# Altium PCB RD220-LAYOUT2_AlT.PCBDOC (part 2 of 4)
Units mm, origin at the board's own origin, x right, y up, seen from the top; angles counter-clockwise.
Board outline 250 x 145 mm, 4 copper layers (TOP, Mid-Layer 1, Mid-Layer 2, BOTTOM), stack 0.711 mm thick; 497 components, 207 nets, 1178 pads, 436 vias.
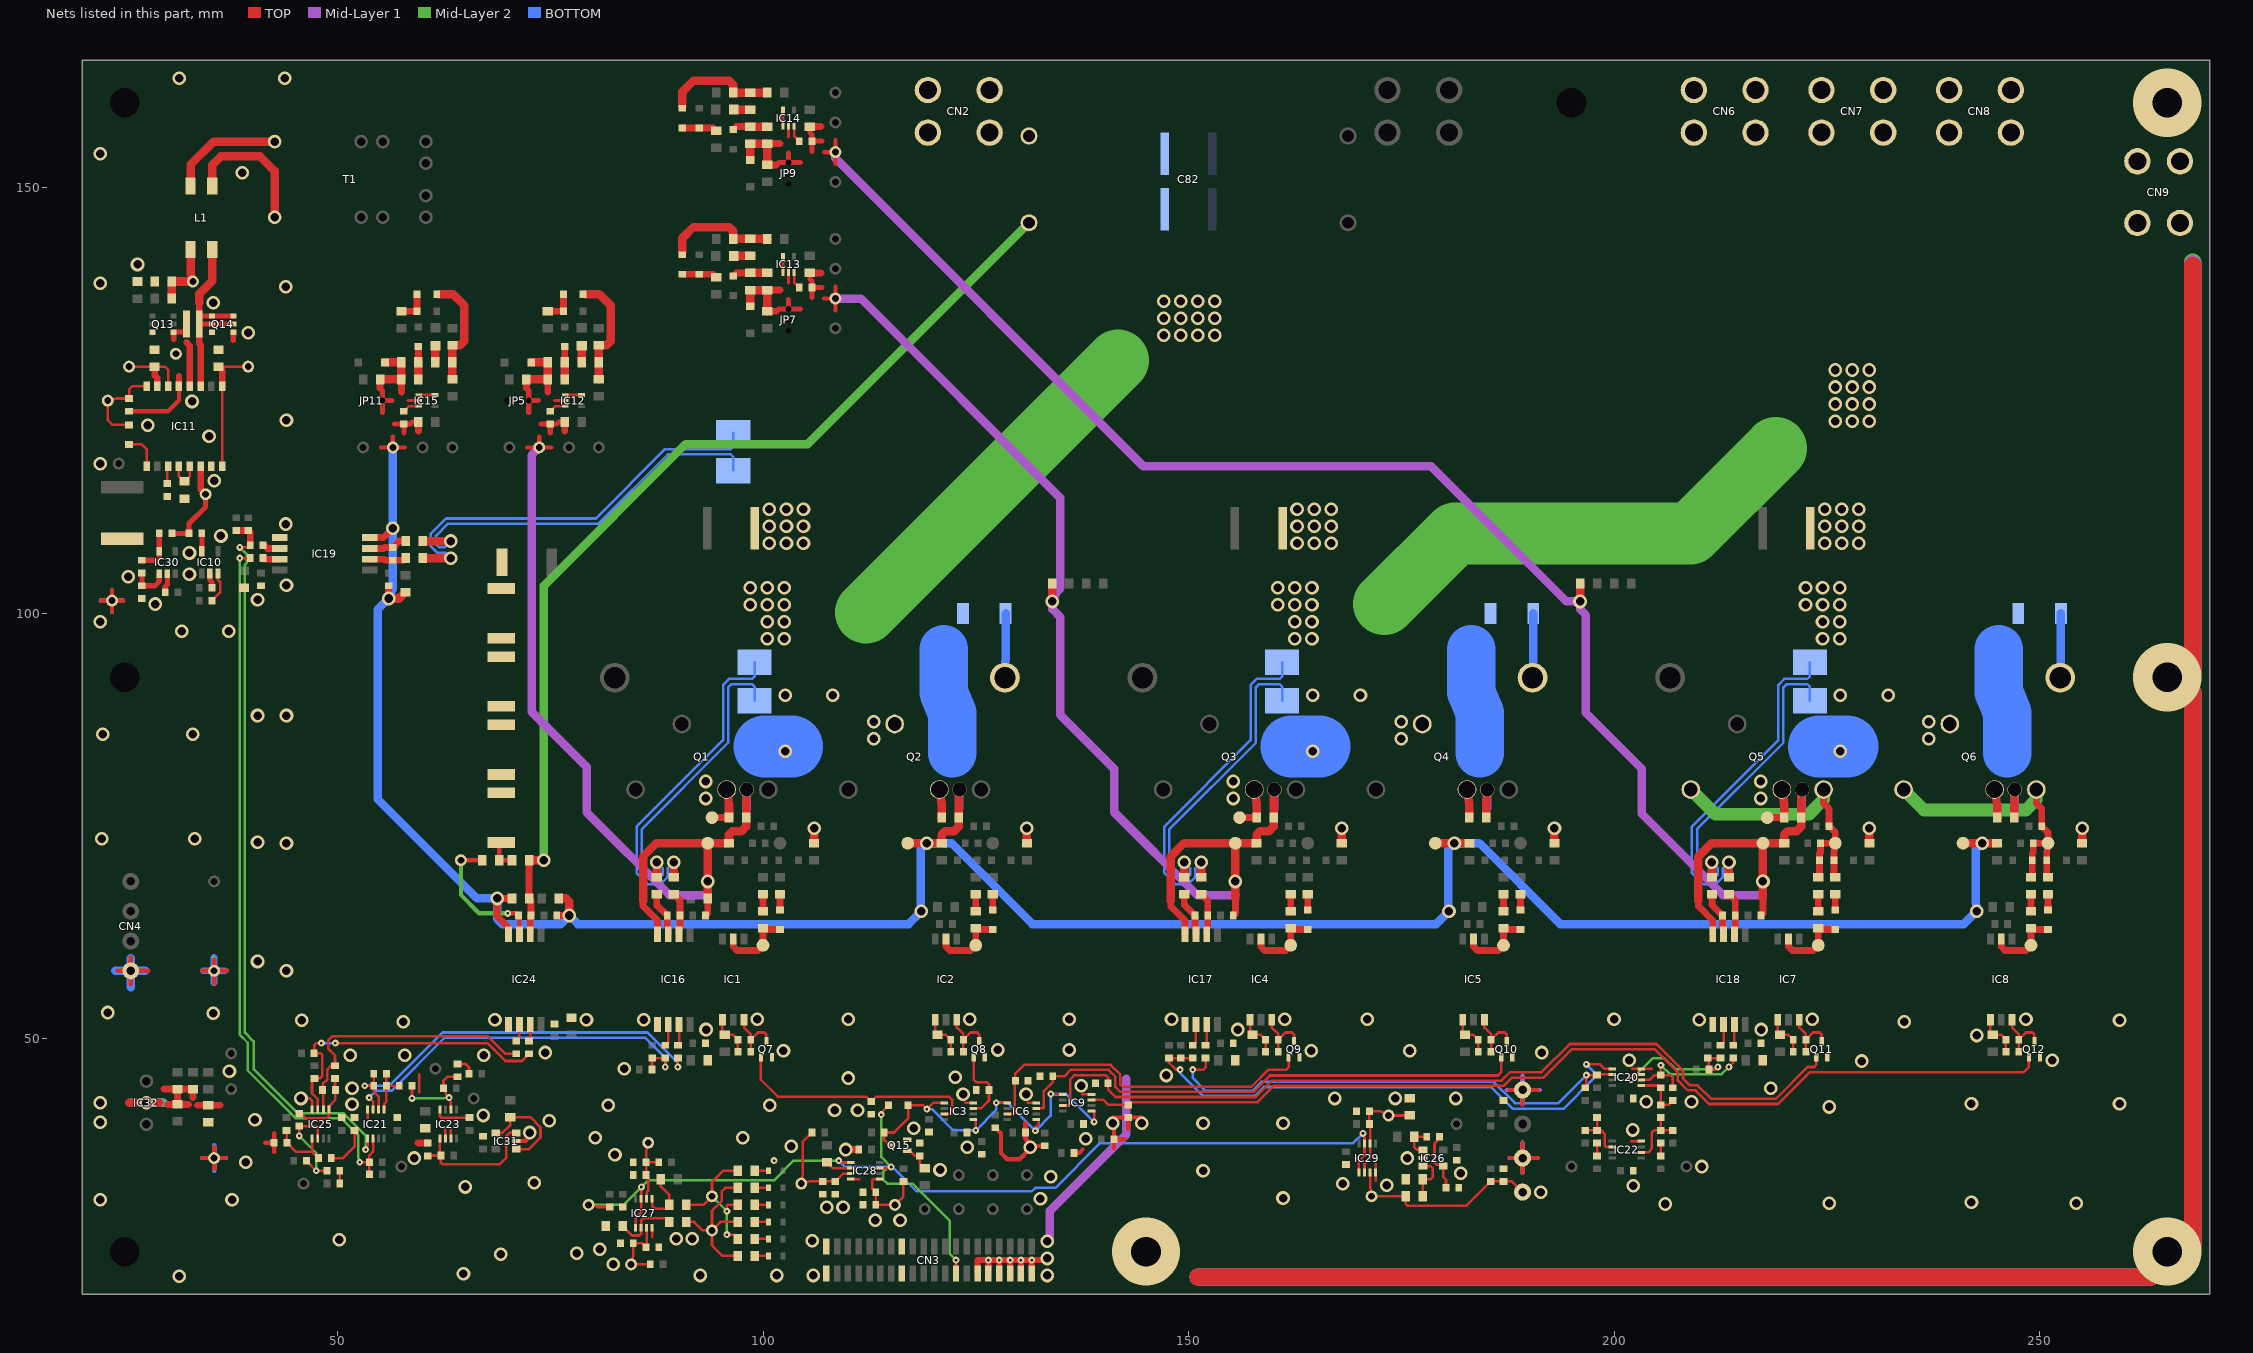
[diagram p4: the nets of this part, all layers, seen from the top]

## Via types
v1: diameter 1.6, hole 1, TOP to BOTTOM, 364 vias
v2: diameter 0.8, hole 0.3, TOP to BOTTOM, 68 vias
v3: diameter 8, hole 3.5, TOP to BOTTOM, 4 vias

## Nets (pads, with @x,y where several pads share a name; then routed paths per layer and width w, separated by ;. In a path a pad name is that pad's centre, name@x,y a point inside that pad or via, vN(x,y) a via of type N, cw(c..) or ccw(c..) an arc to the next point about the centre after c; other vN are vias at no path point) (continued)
G_WH: C145.2 D9.A D10.C Q5.1 Q5.5 R39.1 R40.1 R44.1 TP17.1 | length 35.5
  TOP w0.8: R39.1@224,69 224.15,69.15 D10.C@224.15,71 224.15,71.8 224.25,71.9 R44.1@224.25,73 TP17.1@226,73 ; Q5.5@224.62,79.3 224.62,77.68 225.25,77.05 C145.2@225.25,75 226,74.25 TP17.1@226,73 ; R40.1@226,69 225.85,69.15 D9.A@225.85,71 225.85,71.885 TP17.1@226,73
  Mid-Layer 2 w1.5: Q5.1@209.02,79.3 211.92,76.4 222.9,76.4 224.62,78.12 Q5.5@224.62,79.3
G_WL: C147.2 D11.A D12.C Q6.1 Q6.5 R42.1 R43.1 R45.1 TP20.1 | length 35.1
  TOP w0.8: R42.1@249,69 249.15,69.15 D12.C@249.15,71 249.15,71.8 249.25,71.9 R45.1@249.25,73 TP20.1@251,73 ; Q6.5@249.62,79.3 249.62,77.68 250.25,77.05 C147.2@250.25,75 251,74.25 TP20.1@251,73 ; R43.1@251,69 250.85,69.15 D11.A@250.85,71 250.85,71.885 TP20.1@251,73
  Mid-Layer 2 w1.5: Q6.1@234.02,79.3 236.42,76.9 248.4,76.9 249.62,78.12 Q6.5@249.62,79.3
GND_A: C39.1 C41.1 C42.1 C43.1 C44.1 C46.1 C78.1 C79.1 C98.1 C99.1 C103.1 C104.1 C108.1 C109.1 C113.1 C114.1 C115.1 C117.1 C119.1 C120.1 C121.1 C122.1 C123.1 C128.1 C135.1 C148.1 C149.1 C150.1 C165.2 CN3.29 CN3.31 CN3.33 CN3.35 CN3.37 CN3.39 CN4.4 IC10.2 IC11.7 IC16.5 IC17.5 IC18.5 IC19.5 IC20.4 IC21.4 IC22.4 IC23.4 IC24.5 IC25.4 IC30.2 IC31.2 IC32.2 J2.1 J4.1 Q7.S Q8.S Q9.S Q10.S Q11.S Q12.S Q14.4 R122.2 R154.1 R186.2 R188.2 TP28.1 TP71.1 | length 204
  TOP w0.3: v1(45.7,43) 46.75,43 47.025,42.725 IC25.4@47.025,41.7 ; 53.525,40.7 IC21.4@53.525,41.7 ; 59.6,43.74 59.6,45.85 ; IC23.4@62.025,41.7 62.025,40.925 62.2,40.75 C123.1@65.5,40.75 ; 202,37.975 IC22.4@203.2,37.975 ; 202.15,46.475 IC20.4@203.2,46.475 204.4,46.475
  TOP w0.5: 22.2,101.5 TP28.1@23.5,101.5 ; 23.5,100.25 TP28.1@23.5,101.5 ; 23.5,102.75 TP28.1@23.5,101.5 ; 24.1,58 CN4.4@25.7,58 ; 24.85,101.5 TP28.1@23.5,101.5 ; 25.7,56.4 CN4.4@25.7,58 ; 25.7,59.6 CN4.4@25.7,58 ; 27.8,58 CN4.4@25.7,58 ; 34.1,58 TP71.1@35.5,58 ; 35.5,56.5 TP71.1@35.5,58 ; 35.5,59.3 TP71.1@35.5,58 ; 37,58 TP71.1@35.5,58 ; 41.5,37.8 C165.2@42.55,37.8 ; 42.55,36.7 C165.2@42.55,37.8 ; 42.55,38.9 C165.2@42.55,37.8 ; IC31.2@71,38 72.15,38 v1(72.6,39) ; 187.7,44 J4.1@189.25,44 ; 187.8,36 J2.1@189.25,36 ; 189.25,34.4 J2.1@189.25,36 ; 189.25,37.8 J2.1@189.25,36 ; 189.25,42.3 J4.1@189.25,44 ; 191,36 J2.1@189.25,36 ; 191,44 J4.1@189.25,44
  TOP w0.6: C128.1@29.75,102.5 29.75,103.15 30,103.4 IC30.2@30,104.685 ; IC10.2@35,104.69 35,103.9 35.25,103.65 C39.1@35.25,103 ; 37.75,132.1 Q14.4@37.75,133.05
  TOP w0.7: CN3.29@125.215,22.481 125.215,24.006 v2(126.485,24.006) ; CN3.31@126.485,22.481 v2(126.485,24.006) ; CN3.33@127.755,22.481 v2(127.755,24.006) ; CN3.35@129.025,22.481 v2(129.025,24.006) ; CN3.37@130.295,22.481 v2(130.295,24.006) ; CN3.39@131.565,22.481 v2(131.565,24.006) ; v1(133.4,24.2) 133.206,24.006 v2(131.565,24.006) ; v2(126.485,24.006) v2(127.755,24.006) ; v2(127.755,24.006) v2(129.025,24.006) ; v2(129.025,24.006) v2(130.295,24.006) ; v2(130.295,24.006) v2(131.565,24.006)
  TOP w0.8: 29.6,44.1 C150.1@31.2,44.1 ; 30.05,42.3 C149.1@31.2,42.3 ; 32.5,42.3 C149.1@31.2,42.3 ; 33,43.1 R186.2@33,44.1 C150.1@31.2,44.1 ; 33.533,42.2 R188.2@34.8,42.2 36.2,42.2 ; 59.45,37.75 R122.2@60.6,37.75 ; C149.1@31.2,42.3 C150.1@31.2,44.1
  TOP w1: 25.5,42.5 IC32.2@27.55,42.5 28.964,42.5
  Mid-Layer 1 w0.5: 22.25,101.5 TP28.1@23.5,101.5 ; 23.5,100.3 TP28.1@23.5,101.5 ; 23.5,102.7 TP28.1@23.5,101.5 ; 24.3,58 CN4.4@25.7,58 ; 24.8,101.5 TP28.1@23.5,101.5 ; 25.7,56.7 CN4.4@25.7,58 ; 25.7,59.6 CN4.4@25.7,58 ; 27.1,58 CN4.4@25.7,58 ; 34.3,58 TP71.1@35.5,58 ; 35.5,56.7 TP71.1@35.5,58 ; 35.5,59.2 TP71.1@35.5,58 ; 37,58 TP71.1@35.5,58 ; 187.4,44 J4.1@189.25,44 ; 187.7,36 J2.1@189.25,36 ; 189.25,34.3 J2.1@189.25,36 ; 189.25,37.8 J2.1@189.25,36 ; 189.25,42.3 J4.1@189.25,44 ; 189.25,45.7 J4.1@189.25,44 ; 190.9,36 J2.1@189.25,36 ; 191.3,44 J4.1@189.25,44
  Mid-Layer 1 w1: 26.1,42.5 IC32.2@27.55,42.5 29.1,42.5 ; v1(133.4,26.2) 133.7,26.2 133.7,29.8 142.7,38.8 142.7,45.3
  Mid-Layer 2 w0.5: 22.3,101.5 TP28.1@23.5,101.5 ; 23.5,100.25 TP28.1@23.5,101.5 ; 23.5,102.75 TP28.1@23.5,101.5 ; 24.3,58 CN4.4@25.7,58 ; 24.75,101.5 TP28.1@23.5,101.5 ; 25.7,56.5 CN4.4@25.7,58 ; 25.7,59.5 CN4.4@25.7,58 ; 27.1,58 CN4.4@25.7,58 ; 34.2,58 TP71.1@35.5,58 ; 35.5,56.6 TP71.1@35.5,58 ; 35.5,59.5 TP71.1@35.5,58 ; 36.8,58 TP71.1@35.5,58 ; 187.7,36 J2.1@189.25,36 ; 187.7,44 J4.1@189.25,44 ; 189.25,34.3 J2.1@189.25,36 ; 189.25,37.8 J2.1@189.25,36 ; 189.25,42.4 J4.1@189.25,44 ; 189.25,45.6 J4.1@189.25,44 ; 190.9,44 J4.1@189.25,44 ; 191,36 J2.1@189.25,36
  Mid-Layer 2 w1: 25.65,42.5 IC32.2@27.55,42.5 29.45,42.5
  BOTTOM w0.5: 22.15,101.5 TP28.1@23.5,101.5 23.5,100.2 ; 187.8,36 J2.1@189.25,36 ; 189.25,34.4 J2.1@189.25,36 ; 189.25,37.7 J2.1@189.25,36 ; 189.25,45.6 J4.1@189.25,44 191,44 ; 190.6,36 J2.1@189.25,36
  BOTTOM w0.8: 34.218,58 TP71.1@35.5,58 ; 35.5,56.6 TP71.1@35.5,58 ; 35.5,59.55 TP71.1@35.5,58 ; 36.75,58 TP71.1@35.5,58
  BOTTOM w1: 23.9,58 CN4.4@25.7,58 ; 25.7,56.05 CN4.4@25.7,58 ; 25.7,59.5 CN4.4@25.7,58 ; 25.85,42.5 IC32.2@27.55,42.5 29.55,42.5 ; 27.4,58 CN4.4@25.7,58
  other v1: 206,30.6 225.3,30.7 254.3,30.7 242,30.8 191.4,32 65,32.6 202.25,32.75 210.3,35 59,36 202.2,39.3 74.9,40.4 40.3,40.5 67.1,41 225.3,42 81.8,42.2 100.8,42.2 51.7,42.3 242,42.4 259.4,42.4 22.1,42.5 203.8,42.6 209.1,42.6 51.7,44.2 218.4,44.2 110,45.4 122.6,45.5 147.4,45.7 37.3,46.2 83.7,46.5 229.1,47.4 201.8,47.5 251.5,47.5 51.5,48.1 57.9,48.1 67.2,48.1 74.4,48.4 191.5,48.4 102.4,48.6 164.4,48.6 176,48.6 127.6,48.7 136,48.7 242.6,50.4 93.3,51.1 155.8,51.1 217.3,51.1 57.7,52 234.1,52 45.8,52.2 259.4,52.2 68.5,52.25 79.25,52.25 86,52.25 210,52.25 99.3,52.3 110,52.3 124.3,52.3 136,52.3 148,52.3 161.3,52.3 171,52.3 200,52.3 223.3,52.3 248.4,52.3 35.4,53 23,53.1 44,58 40.6,59.1 44,73 40.6,73.1 22.3,73.5 33.2,73.5 22.4,85.8 33,85.8 40.6,88 44,88 31.7,97.9 37.2,97.9 22.1,99 28.6,101.1 40.6,101.6 44,103.3 25.4,104.3 32.6,104.6 32.6,107.1 36.3,109.1 43.9,110.5 35.5,115.6 22.1,117.6 34.9,120.8 27.7,122.1 44,122.7 32.9,124.9 39.5,133 35.4,136.5 43.9,138.4 22.1,138.8 26.5,141 38.8,151.8 22.1,154 31.4,162.9 43.8,162.9
GND_B: C25.1 C26.2 C31.1 C32.2 C37.1 C38.2 C70.1 C71.1 C72.1 C74.2 C76.1 C77.1 C96.1 C97.1 IC15.2 IC19.4 IC24.4 JP11.3 Q2.4 Q4.4 Q6.4 R62.1 R65.1 R118.1 R119.1 R120.1 TP9.1 TP15.1 TP21.1 TP43.1 ZD4.C | length 350.7
  TOP w0.35: 58.3,125 IC15.2@59.55,125
  TOP w0.5: 55.1,119.5 TP43.1@56.5,119.5 ; 56.5,120.8 TP43.1@56.5,119.5 ; 57.9,119.5 TP43.1@56.5,119.5
  TOP w0.6: 55.27,123.6 JP11.3@55.27,125 ; 55.27,126.18 JP11.3@55.27,125 ; 56.4,125 JP11.3@55.27,125 ; 56.7,122.25 C71.1@57.8,122.25 ; 57.8,121.2 C71.1@57.8,122.25 ; C72.1@59.5,122.5 58.8,122.5 58.55,122.25 C71.1@57.8,122.25
  TOP w0.8: IC19.4@53.8,108.905 55.405,108.905 v1(56.5,110) ; 55,126.45 C74.2@55,127.5 ; v1(56,101.75) C97.1@56,103.25 ; 57.5,126 C70.1@57.5,127.5 ; 59.5,121.4 C72.1@59.5,122.5 ; IC24.4@70.095,62.3 70.095,63.105 68.75,64.45 v1(68.75,66.5) R65.1@70.5,66.5 ; C77.1@75.75,64.5 v1(77.25,64.5)
  TOP w1: C74.2@55,127.5 C70.1@57.5,127.5 R62.1@57.5,129.5 ZD4.C@55.635,129.5 ; v1(56,101.75) 57.25,101.75 C96.1@58,102.5 ; C76.1@76,66.5 76.85,66.5 77.25,66.1 v1(77.25,64.5) ; TP9.1@117,73 v1(119.25,73) C26.2@121,73 121,74 121.4,74.4 122.45,74.4 123,74.95 R118.1@123,76 123,77.945 Q2.4@123.08,79.3 ; C25.1@131,73 v1(131,74.75) ; TP15.1@179,73 v1(181.25,73) C32.2@183,73 ; R119.1@185,76 185,77.945 Q4.4@185.08,79.3 ; C31.1@193,73 v1(193,74.75) ; TP21.1@241,73 v1(243.25,73) C38.2@245,73 ; R120.1@247,76 247,77.945 Q6.4@247.08,79.3 ; C37.1@255,73 v1(255,74.75)
  Mid-Layer 1 w1: 123.08,77.1 Q2.4@123.08,79.3 ; 185.08,77.1 Q4.4@185.08,79.3 ; 247.08,77.1 Q6.4@247.08,79.3
  BOTTOM w1: TP43.1@56.5,119.5 v1(56.5,110) 56.5,102.841 v1(56,101.75) 54.75,100.5 54.75,78.15 66.4,66.5 v1(68.75,66.5) 68.75,64.1 69.35,63.5 76.25,63.5 v1(77.25,64.5) 78.25,63.5 117.1,63.5 v1(118.6,65) 118.55,66.199 118.55,72.3 v1(119.25,73) 122.15,73 131.65,63.5 179.1,63.5 v1(180.6,65) 180.5,66.196 180.5,72.25 v1(181.25,73) 184.175,73 193.675,63.5 241.1,63.5 v1(242.6,65) 242.5,66.196 242.5,72.25 v1(243.25,73)
GND_D: C88.1 C89.1 C90.1 C91.1 C92.1 C93.1 C94.1 C116.1 C118.1 C124.1 C125.1 C126.1 CN3.1 CN3.2 CN3.15 CN3.16 IC3.4 IC6.4 IC9.4 IC26.2 IC27.4 IC28.4 IC29.4 Q15.S R85.2 R87.2 R89.2 R91.2 R96.2 R98.2 R109.2 R113.2 R115.1 R162.2 R163.2 R164.2 R167.2 R170.2 R171.2 R172.2 R175.2 R178.2 R179.2 R180.2 R183.2 R188.1 TP73.1 | length 53.5
  TOP w0.3: 86.975,26.75 IC27.4@86.975,27.8 ; IC28.4@110.3,33.525 111.3,33.525 ; 123.75,42.475 IC3.4@124.7,42.475 ; 131.1,42.475 IC6.4@132.1,42.475 ; 137.5,43.475 IC9.4@138.6,43.475 ; 171.975,33.35 IC29.4@171.975,34.3 171.975,35.3
  TOP w0.5: 34.1,36 TP73.1@35.5,36 ; 35.5,34.7 TP73.1@35.5,36 ; 35.5,37.3 TP73.1@35.5,36 ; 36.8,36 TP73.1@35.5,36 ; R171.2@127.3,39.55 127.95,38.9 127.95,36.6 128.7,35.85 130.15,35.85 130.63,36.33 v1(131.4,37.25) 132.583,37.45 R170.2@133.1,37.45 ; R179.2@136.55,36.6 137.15,36.6 137.55,37 ; 141.25,37.15 R178.2@141.25,38.2 ; 142.5,38.2 R178.2@141.25,38.2 ; 142.9,39.45 R183.2@142.9,40.75 ; v1(144.5,40.1) 144.5,40.75 R183.2@142.9,40.75 ; R178.2@141.25,38.2 141.25,39.95 v1(141.1,40.1) 141.1,40.75 R183.2@142.9,40.75
  TOP w0.6: 130.85,40.05 C125.1@130.85,39 130.85,38.317 v1(131.4,37.25)
  TOP w0.8: v1(109.7,37) C89.1@111.25,37
  Mid-Layer 1 w0.5: 34.2,36 TP73.1@35.5,36 ; 35.5,34.8 TP73.1@35.5,36 ; 35.5,37.3 TP73.1@35.5,36 ; 36.9,36 TP73.1@35.5,36
  Mid-Layer 2 w0.5: 34.2,36 TP73.1@35.5,36 ; 35.5,34.7 TP73.1@35.5,36 ; 35.5,37.3 TP73.1@35.5,36 ; 36.5,36 TP73.1@35.5,36
  BOTTOM w0.5: 34.1,36 TP73.1@35.5,36 ; 35.5,34.5 TP73.1@35.5,36 ; 35.5,37.5 TP73.1@35.5,36 ; 36.9,36 TP73.1@35.5,36
  other v1: 31.4,22.1 92.6,22.2 101.6,22.2 105.9,22.2 133.4,22.2 64.8,22.4 82.4,23.5 69.2,24.7 78.1,24.8 80.8,25.3 105.8,26.3 50.2,26.4 89.8,26.5 91.7,26.5 113.2,28.7 116.1,28.7 107.5,30.2 109.4,30.2 22.1,31.1 37.6,31.1 132.6,31.2 161.1,31.3 173.3,32.8 168.1,33 73.1,33.1 133.8,33.8 182,34.2 151.7,34.5 120.8,34.6 39.2,35.5 175.7,36 82.6,36.4 124,37.25 103.3,37.4 137.9,38.25 80.3,38.4 97.6,38.4 117.7,39.5 151.7,40.1 161.1,40.1 22.1,40.2 108.4,41.6 111.1,41.6 167.2,43 174.3,43 181.4,43 123.5,43.5 130.9,43.5 137.4,44.5
  other v2: 101.3,35.7
GND_DC: C75.1 C82.3 C82.4 C84.1 C85.1 CN2.1 CN2.2 CN2.3 CN2.4 IC24.2 R4.1 R65.2 R71.2 R102.2 | length 166.6
  TOP w0.8: R71.2@72.5,71 R65.2@72.5,66.5 72.75,66.25 C75.1@72.75,64.5 72.635,64.385 IC24.2@72.635,62.3
  TOP w1: R102.2@60,106.5 v1(63.3,106.5) ; R71.2@72.5,71 v1(74.25,71)
  Mid-Layer 2 w1: v1(74.25,71) 74.25,103.25 90.9,119.9 105.25,119.9 C82.3@131.25,145.9
  BOTTOM w0.3: v1(63.3,106.5) 62.65,107.15 61.7,107.15 60.95,107.9 60.95,109.35 62.75,111.15 80.35,111.15 88.5,119.3 96.2,119.3 96.5,119.6 R4.1@96.5,121.2
GND_F: CN9.1 CN9.2 CN9.3 CN9.4 | length 899.3
  TOP w2: 151.1,22 v3@263.1,22 ; v3@268,25.7 v3@268,90.7 ; v3@268,93.2 268,140.9
  Mid-Layer 1 w2: 151.1,22 v3@263.1,22 ; v3@268,25.7 v3@268,90.7 ; v3@268,93.2 268,141.05
  Mid-Layer 2 w2: 151.1,22 v3@263.1,22 ; v3@268,25.7 v3@268,90.7 ; v3@268,93.2 268,141.3
  BOTTOM w2: 151.1,22 v3@263.1,22 ; v3@268,25.7 v3@268,90.7 ; v3@268,93.2 268,140.9
  other v3: 145,25 265,25 265,92.5 265,160
GND_U: C22.1 C23.2 C49.1 C50.1 C51.1 C53.2 C101.1 C102.1 IC12.2 IC16.4 JP5.3 Q1.4 R27.1 R53.1 TP6.1 TP31.1 ZD1.C | length 127.7
  TOP w0.35: 75.5,125 IC12.2@76.75,125
  TOP w0.5: 72.3,119.5 TP31.1@73.7,119.5 ; 73.7,120.8 TP31.1@73.7,119.5 ; 75.1,119.5 TP31.1@73.7,119.5
  TOP w0.6: 72.47,123.6 JP5.3@72.47,125 ; 72.47,126.18 JP5.3@72.47,125 ; 73.6,125 JP5.3@72.47,125 ; 73.9,122.25 C50.1@75,122.25 ; 75,121.2 C50.1@75,122.25 ; C51.1@76.7,122.5 76,122.5 75.75,122.25 C50.1@75,122.25
  TOP w0.8: 72.2,126.45 C53.2@72.2,127.5 ; 74.7,126 C49.1@74.7,127.5 ; 76.7,121.4 C51.1@76.7,122.5 ; 85.9,66.222 85.9,65.6 87.595,63.905 IC16.4@87.595,62.3 ; C102.1@93.25,64.5 93.5,64.75 C101.1@93.5,66.5
  TOP w1: C53.2@72.2,127.5 C49.1@74.7,127.5 R53.1@74.7,129.5 ZD1.C@72.835,129.5 ; 85.9,66.222 85.9,71.425 87.475,73 TP6.1@93.5,73 ; C101.1@93.5,66.5 v1(93.5,68.5) TP6.1@93.5,73 ; Q1.4@98.08,79.3 98,77.945 R27.1@98,76 98,74.95 97.45,74.4 96.4,74.4 96,74 C23.2@96,73 TP6.1@93.5,73 ; C22.1@106,73 v1(106,74.75)
  Mid-Layer 1 w1: TP31.1@73.7,119.5 72.8,118.6 72.8,88.45 79.27,81.98 79.27,76.63 89,66.9 93,66.9 ; 98.08,77 Q1.4@98.08,79.3
GND_V: C28.1 C29.2 C56.1 C57.1 C58.1 C60.2 C106.1 C107.1 IC13.2 IC17.4 JP7.1 Q3.4 R28.1 R56.1 TP12.1 TP35.1 ZD2.C | length 161.1
  TOP w0.35: 103,138.8 IC13.2@103,140.05
  TOP w0.5: 107.2,137 TP35.1@108.5,137 ; 108.5,135.6 TP35.1@108.5,137 ; 108.5,138.4 TP35.1@108.5,137
  TOP w0.6: 101.82,135.77 JP7.1@103,135.77 ; 103,136.9 JP7.1@103,135.77 ; 104.4,135.77 JP7.1@103,135.77 ; C58.1@105.5,140 105.5,139.3 105.75,139.05 C57.1@105.75,138.3 ; 105.75,137.1 C57.1@105.75,138.3 ; 106.9,138.3 C57.1@105.75,138.3
  TOP w0.8: C60.2@100.5,135.5 101.55,135.5 ; C56.1@100.5,138 102,138 ; C58.1@105.5,140 106.8,140 ; 147.9,66.222 147.9,65.6 149.595,63.905 IC17.4@149.595,62.3 ; C107.1@155.25,64.5 155.5,64.75 155.5,66.5
  TOP w1: ZD2.C@98.5,136.135 R56.1@98.5,138 C56.1@100.5,138 C60.2@100.5,135.5 ; v1(134,101.4) C106.1@134,103.5 ; 147.9,66.222 147.9,71.425 149.475,73 TP12.1@155.5,73 ; 155.5,66.5 v1(155.5,68.5) TP12.1@155.5,73 ; Q3.4@160.08,79.3 160,77.945 R28.1@160,76 160,74.95 159.45,74.4 158.4,74.4 158,74 C29.2@158,73 TP12.1@155.5,73 ; C28.1@168,73 v1(168,74.75)
  Mid-Layer 1 w1: TP35.1@108.5,137 111.5,137 134.93,113.57 134.93,102.93 134.494,102.494 v1(134,101.4) 134,100.5 134.93,99.57 134.93,88.07 141.27,81.73 141.27,76.63 151,66.9 155.5,66.9 ; 160.08,77 Q3.4@160.08,79.3
GND_W: C34.1 C35.2 C63.1 C64.1 C65.1 C67.2 C111.1 C112.1 IC14.2 IC18.4 JP9.1 Q5.4 R29.1 R59.1 TP18.1 TP39.1 ZD3.C | length 222.5
  TOP w0.35: 103,156 IC14.2@103,157.25
  TOP w0.5: 107.2,154.2 TP39.1@108.5,154.2 ; 108.5,152.8 TP39.1@108.5,154.2 ; 108.5,155.6 TP39.1@108.5,154.2
  TOP w0.6: 101.82,152.97 JP9.1@103,152.97 ; 103,154.1 JP9.1@103,152.97 ; 104.4,152.97 JP9.1@103,152.97 ; C65.1@105.5,157.2 105.5,156.5 105.75,156.25 C64.1@105.75,155.5 ; 105.75,154.3 C64.1@105.75,155.5 ; 106.9,155.5 C64.1@105.75,155.5
  TOP w0.8: C67.2@100.5,152.7 101.55,152.7 ; C63.1@100.5,155.2 102,155.2 ; C65.1@105.5,157.2 106.8,157.2 ; 209.9,66.222 209.9,65.6 211.595,63.905 IC18.4@211.595,62.3 ; C112.1@217.25,64.5 217.5,64.75 217.5,66.5
  TOP w1: ZD3.C@98.5,153.335 R59.1@98.5,155.2 C63.1@100.5,155.2 C67.2@100.5,152.7 ; v1(196,101.4) C111.1@196,103.5 ; 209.9,66.222 209.9,71.425 211.475,73 TP18.1@217.5,73 ; 217.5,66.5 v1(217.5,68.5) TP18.1@217.5,73 ; Q5.4@222.08,79.3 222,77.945 R29.1@222,76 222,74.95 221.45,74.4 220.4,74.4 220,74 C35.2@220,73 TP18.1@217.5,73 ; C34.1@230,73 v1(230,74.75)
  Mid-Layer 1 w1: TP39.1@108.5,154.2 108.5,153.475 144.675,117.3 178.5,117.3 194.4,101.4 v1(196,101.4) 196,100.5 196.7,99.8 196.7,88.3 203.27,81.73 203.27,76.43 212.8,66.9 217.5,66.9 ; 222.08,77 Q5.4@222.08,79.3
IDCP: C86.1 C87.1 C127.1 Q2.3 Q4.3 Q6.3 R4.2 R101.2 R118.2 R119.2 R120.2 R158.1 R159.1 R160.1 | length 94.4
  TOP w1: R101.2@60,108.5 v1(63.3,108.5) ; Q2.3@120.72,79.3 121,77.59 R118.2@121,76 ; Q4.3@182.72,79.3 183,77.59 R119.2@183,76 ; Q6.3@244.72,79.3 245,77.59 R120.2@245,76
  BOTTOM w0.3: v1(63.3,108.5) 62.55,107.75 61.95,107.75 61.55,108.15 61.55,109.1 63,110.55 80.65,110.55 88.8,118.7 96.2,118.7 96.5,118.4 R4.2@96.5,116.8
  BOTTOM w5.7: 121.22,95.8 121.22,90.733 122.21,88.343 122.21,83.546 ; 183.22,95.8 183.22,90.733 184.21,88.343 184.21,83.546 ; 245.22,95.8 245.22,90.733 246.21,88.343 246.21,83.546
  other v1: 100.75,108.25 102.75,108.25 104.75,108.25 162.75,108.25 164.75,108.25 166.75,108.25 224.75,108.25 226.75,108.25 228.75,108.25 100.75,110.25 102.75,110.25 104.75,110.25 162.75,110.25 164.75,110.25 166.75,110.25 224.75,110.25 226.75,110.25 228.75,110.25 100.75,112.25 102.75,112.25 104.75,112.25 162.75,112.25 164.75,112.25 166.75,112.25 224.75,112.25 226.75,112.25 228.75,112.25
IUN: CN6.1 CN6.2 CN6.3 CN6.4 R1.2 R104.2 | length 82.3
  TOP w1: R104.2@89.5,69 v1(89.5,70.75)
  Mid-Layer 2 w7.3: 112.1,100.1 141.7,129.7
  BOTTOM w0.3: v1(89.5,70.75) 88.8,70.05 88.8,69.05 87.9,68.15 86.5,68.15 85.15,69.5 85.15,74.95 95.3,85.1 95.3,91.6 96,92.3 98.7,92.3 99,92.6 R1.2@99,94.25
  other v1: 100.5,97 102.5,97 100.5,99 102.5,99 98.5,101 100.5,101 102.5,101 98.5,103 100.5,103 102.5,103 147.1,132.7 149.1,132.7 151.1,132.7 153.1,132.7 147.1,134.7 149.1,134.7 151.1,134.7 153.1,134.7 147.1,136.7 149.1,136.7 151.1,136.7 153.1,136.7
IUP: Q1.3 Q2.2 R1.1 R27.2 R103.2 TP1.1 | length 46
  TOP w0.8: TP1.1@94,76 R27.2@96,76
  TOP w1: R103.2@87.5,69 v1(87.5,70.75) ; Q1.3@95.72,79.3 96,77.59 R27.2@96,76
  BOTTOM w0.3: v1(87.5,70.75) 88.2,70.05 88.2,69.3 87.65,68.75 86.75,68.75 85.75,69.75 85.75,74.65 95.9,84.8 95.9,91.3 96.3,91.7 98.7,91.7 99,91.4 R1.1@99,89.75
  BOTTOM w7.3: 100.15,84.35 103.403,84.35
  other v1: 93.25,78.25 93.25,80.25 102.6,83.8 113,85.25 113,87.25 102.6,90.4 108.2,90.4
IVN: CN7.1 CN7.2 CN7.3 CN7.4 R2.2 R106.2 | length 94
  TOP w1: R106.2@151.5,69 v1(151.5,70.75)
  Mid-Layer 2 w7.3: 173,101.1 181.3,109.4 209,109.4 219,119.4
  BOTTOM w0.3: v1(151.5,70.75) 150.8,70.05 150.8,69.05 149.9,68.15 148.5,68.15 147.15,69.5 147.15,74.95 157.3,85.1 157.3,91.6 158,92.3 160.7,92.3 161,92.6 R2.2@161,94.25
  other v1: 162.5,97 164.5,97 162.5,99 164.5,99 160.5,101 162.5,101 164.5,101 160.5,103 162.5,103 164.5,103 226,122.6 228,122.6 230,122.6 226,124.6 228,124.6 230,124.6 226,126.6 228,126.6 230,126.6 226,128.6 228,128.6 230,128.6
IVP: Q3.3 Q4.2 R2.1 R28.2 R105.2 TP2.1 | length 46
  TOP w0.8: TP2.1@156,76 R28.2@158,76
  TOP w1: R105.2@149.5,69 v1(149.5,70.75) ; Q3.3@157.72,79.3 158,77.59 R28.2@158,76
  BOTTOM w0.3: v1(149.5,70.75) 150.2,70.05 150.2,69.3 149.65,68.75 148.75,68.75 147.75,69.75 147.75,74.65 157.9,84.8 157.9,91.3 158.3,91.7 160.7,91.7 161,91.4 R2.1@161,89.75
  BOTTOM w7.3: 162.1,84.35 165.403,84.35
  other v1: 155.25,78.25 155.25,80.25 164.6,83.8 175,85.25 175,87.25 164.6,90.4 170.2,90.4
IWN: CN8.1 CN8.2 CN8.3 CN8.4 R3.2 R108.2 | length 40.4
  TOP w1: R108.2@213.5,69 v1(213.5,70.75)
  BOTTOM w0.3: v1(213.5,70.75) 212.8,70.05 212.8,69.05 211.9,68.15 210.5,68.15 209.15,69.5 209.15,74.95 219.3,85.1 219.3,91.6 220,92.3 222.7,92.3 223,92.6 R3.2@223,94.25
  other v1: 224.5,97 226.5,97 224.5,99 226.5,99 222.5,101 224.5,101 226.5,101 222.5,103 224.5,103 226.5,103
IWP: Q5.3 Q6.2 R3.1 R29.2 R107.2 TP3.1 | length 46
  TOP w0.8: TP3.1@218,76 R29.2@220,76
  TOP w1: R107.2@211.5,69 v1(211.5,70.75) ; Q5.3@219.72,79.3 220,77.59 R29.2@220,76
  BOTTOM w0.3: v1(211.5,70.75) 212.2,70.05 212.2,69.3 211.65,68.75 210.75,68.75 209.75,69.75 209.75,74.65 219.9,84.8 219.9,91.3 220.3,91.7 222.7,91.7 223,91.4 R3.1@223,89.75
  BOTTOM w7.3: 224.1,84.35 227.403,84.35
  other v1: 217.25,78.25 217.25,80.25 226.6,83.8 237,85.25 237,87.25 226.6,90.4 232.2,90.4
nBRK: D43.A IC3.1 IC3.5 IC6.1 IC6.5 IC9.1 IC9.5 Q15.D R100.2 | length 47.8
  TOP w0.3: Q15.D@115.05,37.5 114.85,37.5 114.25,38.1 R100.2@114.25,39 115.4,39 117.05,40.65 D43.A@117.05,42.2 118.8,42.2 v2(119.25,41.75) 119.975,42.475 IC3.5@121.3,42.475 ; IC3.1@124.7,40.525 124.925,40.525 125,40.45 v2(125,39.25) ; v2(127.4,42.5) 127.924,42.475 IC6.5@128.7,42.475 ; v2(132,39.2) 132,39.6 132.4,40 132.4,40.45 132.325,40.525 IC6.1@132.1,40.525 ; v2(133.8,43.525) 134.323,43.475 IC9.5@135.2,43.475 ; IC9.1@138.6,41.525 138.825,41.525 138.9,41.45 v2(138.9,40.25)
  BOTTOM w0.3: v2(119.25,41.75) 119.85,41.75 122.35,39.25 v2(125,39.25) 127.4,41.65 v2(127.4,42.5) 128.7,42.5 v2(132,39.2) 133.8,41 v2(133.8,43.525) 135.625,43.525 v2(138.9,40.25)
nEMG: CN3.25 D43.C IC27.1 IC27.7 IC28.1 IC28.7 IC29.1 IC29.7 R99.2 TP53.1 | length 139.1
  TOP w0.3: TP53.1@79.5,30.5 80.52,30.25 R99.2@82,30.25 ; IC27.1@85.025,27.8 85.025,28.925 85.675,29.575 IC27.7@85.675,31.2 85.675,32.076 v2(85.7,32.6) ; v2(108.9,35.7) 109.374,35.475 IC28.1@110.3,35.475 ; IC28.7@113.7,34.825 114.54,34.825 v2(115.05,34.95) ; v2(113.9,41.1) 114.125,41.575 D43.C@114.75,42.2 ; CN3.25@122.675,22.481 v2(122.675,24.006) ; IC29.1@170.025,34.3 170.025,35.625 170.675,36.275 IC29.7@170.675,37.7 170.675,38.405 v2(170.5,38.9)
  Mid-Layer 2 w0.3: TP53.1@79.5,30.5 83.6,30.5 v2(85.7,32.6) 86.475,33.375 101.275,33.375 103.6,35.7 v2(108.9,35.7) ; v2(113.9,41.1) 113.9,36.1 v2(115.05,34.95) 114.489,34.739 114.1,34.35 114.1,33.5 114.6,33 117.556,33 121.95,28.606 121.95,24.731 v2(122.675,24.006)
  BOTTOM w0.3: v2(108.9,35.7) 109.65,34.95 v2(115.05,34.95) 115.489,34.661 118.05,32.1 131.6,32.1 132,32.5 134.35,32.5 139.6,37.75 169.35,37.75 v2(170.5,38.9)
SIGN0024: C136.2 IC1.1 R13.1 R165.1 | length 5.1
  TOP w0.3: IC1.1@95.23,52.25 95.23,50.77 R13.1@95.5,50.5 96.45,50.5 C136.2@97.05,49.9 R165.1@97.05,48.5
SIGN0031: C140.1 IC4.3 Q9.D R173.2 | length 7.1
  TOP w0.3: IC4.3@159.77,52.25 159.77,51.33 160.55,50.55 C140.1@160.55,49.9 ; R173.2@160.55,48.5 C140.1@160.55,49.9 ; Q9.D@162.4,49.75 162.4,50.5 162.15,50.75 161.4,50.75 C140.1@160.55,49.9
SIGN0035: C142.1 IC5.3 Q10.D R176.2 | length 7.1
  TOP w0.3: IC5.3@184.77,52.25 184.77,51.33 185.55,50.55 C142.1@185.55,49.9 ; R176.2@185.55,48.5 C142.1@185.55,49.9 ; Q10.D@187.4,49.75 187.4,50.5 187.15,50.75 186.4,50.75 C142.1@185.55,49.9
SIGN0041: C144.2 IC7.1 R38.1 R181.1 | length 5.1
  TOP w0.3: IC7.1@219.23,52.25 219.23,50.77 R38.1@219.5,50.5 220.45,50.5 C144.2@221.05,49.9 R181.1@221.05,48.5
SIGN0042: C144.1 IC7.3 Q11.D R181.2 | length 7.1
  TOP w0.3: IC7.3@221.77,52.25 221.77,51.33 222.55,50.55 C144.1@222.55,49.9 ; R181.2@222.55,48.5 C144.1@222.55,49.9 ; Q11.D@224.4,49.75 224.4,50.5 224.15,50.75 223.4,50.75 C144.1@222.55,49.9
SIGN0043: IC9.3 Q12.G R183.1 | length 119.3
  TOP w0.3: IC9.3@138.6,42.825 140,42.825 140.575,42.25 R183.1@142.9,42.25 143.225,42.575 158.125,42.575 160.05,44.5 187.05,44.5 188,45.45 191.7,45.45 195.05,48.8 204.731,48.8 207.5,46.031 207.5,45.107 208.657,43.95 209.581,43.95 211.181,42.35 219.25,42.35 223,46.1 248.15,46.1 248.75,46.7 Q12.G@248.75,47.85
SIGN0045: C146.1 IC8.3 Q12.D R184.2 | length 7.1
  TOP w0.3: IC8.3@246.77,52.25 246.77,51.33 247.55,50.55 C146.1@247.55,49.9 ; R184.2@247.55,48.5 C146.1@247.55,49.9 ; Q12.D@249.4,49.75 249.4,50.5 249.15,50.75 248.4,50.75 C146.1@247.55,49.9
SIGN0049: C146.2 IC8.1 R41.1 R184.1 | length 5.1
  TOP w0.3: IC8.1@244.23,52.25 244.23,50.77 R41.1@244.5,50.5 245.45,50.5 C146.2@246.05,49.9 R184.1@246.05,48.5
SIGN0051: IC10.3 R46.1 | length 3.7
  TOP w0.3: R46.1@35.25,101.5 36.2,102.45 36.2,103.7 35.95,103.95 IC10.3@35.95,104.69
SIGN0054: IC10.5 J13.1 | length 2.1
  TOP w0.6: IC10.5@34.05,107.31 J13.1@34.05,109.4
SIGN0055: D13.A IC11.1 | length 4.3
  TOP w0.3: D13.A@25.5,119.85 27,119.85 27.555,119.295 IC11.1@27.555,117.301
SIGN0059: C41.2 IC11.4 IC11.5 | length 4.1
  TOP w0.3: IC11.4@31.365,117.301 31.365,116.135 C41.2@32,115.5 32.635,116.135 IC11.5@32.635,117.301
SIGN0062: DS1.A R51.1 | length 2
  TOP w1: R51.1@78.7,129.5 DS1.A@78.7,131.45
SIGN0063: C49.2 D16.C IC12.1 IC12.5 R53.2 | length 5.8
  TOP w0.35: IC12.1@76.75,125.65 IC12.5@78.65,125.65
  TOP w0.8: R53.2@76.7,129.5 D16.C@76.7,131.35
  TOP w1: C49.2@76.7,127.5 R53.2@76.7,129.5
SIGN0064: C48.2 D14.C R51.2 R52.1 | length 13.3
  TOP w1: D14.C@79.111,137.5 80.775,137.5 82.1,136.175 82.1,132 81.6,131.5 C48.2@80.7,131.5 R51.2@80.7,129.5 R52.1@80.7,127.5
SIGN0071: C62.2 D23.C R57.2 R58.1 | length 13.3
  TOP w1: D23.C@90.5,159.611 90.5,161.275 91.825,162.6 96,162.6 96.5,162.1 C62.2@96.5,161.2 R57.2@98.5,161.2 R58.1@100.5,161.2
SIGN0073: DS3.A R57.1 | length 2
  TOP w1: DS3.A@96.55,159.2 R57.1@98.5,159.2
SIGN0074: C70.2 D29.C IC15.1 IC15.5 R62.2 | length 5.7
  TOP w0.35: IC15.1@59.55,125.65 IC15.5@61.45,125.65
  TOP w0.8: R62.2@59.5,129.5 D29.C@59.5,131.35
  TOP w1: C70.2@59.5,127.5 R62.2@59.5,129.5
SIGN0078: C61.2 D23.A D24.C | length 4.1
  TOP w0.8: D23.A@90.5,157.05 D24.C@92.5,157.05 94.15,157.05 C61.2@94.5,156.7
SIGN00195: HS1.1 R158.2 | length 7.5
  BOTTOM w1: HS1.1@128.42,92.54 128.5,95.164 R158.2@128.5,100
SIGN00196: HS2.1 R159.2 | length 7.5
  BOTTOM w1: HS2.1@190.42,92.54 190.5,95.164 R159.2@190.5,100
SIGN00197: HS3.1 R160.2 | length 7.5
  BOTTOM w1: HS3.1@252.42,92.54 252.5,95.164 R160.2@252.5,100
SIGN00213: C139.1 IC2.3 Q8.D R168.2 | length 7.1
  TOP w0.3: IC2.3@122.77,52.25 122.77,51.33 123.55,50.55 C139.1@123.55,49.9 ; R168.2@123.55,48.5 C139.1@123.55,49.9 ; Q8.D@125.4,49.75 125.4,50.5 125.15,50.75 124.4,50.75 C139.1@123.55,49.9
SIGN00215: C139.2 IC2.1 R16.1 R168.1 | length 5.1
  TOP w0.3: IC2.1@120.23,52.25 120.23,50.77 R16.1@120.5,50.5 121.45,50.5 C139.2@122.05,49.9 R168.1@122.05,48.5
SIGN00238: C136.1 IC1.3 Q7.D R165.2 | length 7.1
  TOP w0.3: IC1.3@97.77,52.25 97.77,51.33 98.55,50.55 C136.1@98.55,49.9 ; R165.2@98.55,48.5 C136.1@98.55,49.9 ; Q7.D@100.4,49.75 100.4,50.5 100.15,50.75 99.4,50.75 C136.1@98.55,49.9
SIGN00241: IC3.7 Q7.G R164.1 | length 29.1
  TOP w0.3: Q7.G@99.75,47.85 99.75,45.2 101.75,43.2 112.15,43.2 R164.1@112.7,42.65 113.25,43.2 121.85,43.2 122.25,42.8 122.25,41.325 122.1,41.175 IC3.7@121.3,41.175
SIGN00244: IC3.3 Q8.G R167.1 | length 8.8
  TOP w0.3: IC3.3@124.7,41.825 125.625,41.825 126.55,42.75 R167.1@126.55,44 126.55,44.65 126.3,44.9 125.1,44.9 124.753,45.247 124.753,47.847 Q8.G@124.75,47.85
SIGN00247: D41.C IC1.5 R166.1 TP4.1 | length 8.7
  TOP w0.8: IC1.5@96.5,61.75 96.5,60.85 96.95,60.4 99.4,60.4 TP4.1@100,61 100,62.85 D41.C@102,62.85
SIGN00248: D41.A R15.2 | length 1.9
  TOP w0.8: D41.A@102,65.15 R15.2@102,67
SIGN00250: D42.A R18.2 | length 1.9
  TOP w0.8: D42.A@127,65.15 R18.2@127,67
SIGN00251: R14.2 R166.2 | length 1.9
  TOP w0.8: R166.2@100,65.15 R14.2@100,67
SIGN00252: D42.C IC2.5 R169.1 TP7.1 | length 8.9
  TOP w0.8: IC2.5@121.5,61.75 121.5,60.85 121.95,60.4 124.4,60.4 TP7.1@125,61 R169.1@125,63 125.15,62.85 D42.C@127,62.85
SIGN00253: R17.2 R169.2 | length 2
  TOP w0.8: R169.2@125,65 R17.2@125,67
SIGN00310: IC6.7 Q9.G R172.1 | length 42
  TOP w0.3: IC6.7@128.7,41.175 129.475,41.175 129.6,41.3 129.6,45.05 R172.1@129.65,45.1 129.65,45.95 130.65,46.95 140.85,46.95 142,45.8 142,44.625 142.25,44.375 157.375,44.375 159.35,46.35 161.45,46.35 161.75,46.65 Q9.G@161.75,47.85
SIGN00316: IC6.3 Q10.G R175.1 | length 62.5
  TOP w0.3: IC6.3@132.1,41.825 132.875,41.825 133,41.95 133,43.9 134.05,44.95 R175.1@134.05,45.6 135.4,45.6 136.15,46.35 140.6,46.35 141.4,45.55 141.4,44.35 141.975,43.775 157.625,43.775 159.55,45.7 186.35,45.7 186.75,46.1 Q10.G@186.75,47.85
SIGN00319: C140.2 IC4.1 R30.1 R173.1 | length 5.1
  TOP w0.3: IC4.1@157.23,52.25 157.23,50.77 R30.1@157.5,50.5 158.45,50.5 C140.2@159.05,49.9 R173.1@159.05,48.5
SIGN00323: C142.2 IC5.1 R33.1 R176.1 | length 5.1
  TOP w0.3: IC5.1@182.23,52.25 182.23,50.77 R33.1@182.5,50.5 183.45,50.5 C142.2@184.05,49.9 R176.1@184.05,48.5
SIGN00330: D37.A R32.2 | length 1.9
  TOP w0.8: D37.A@164,65.15 R32.2@164,67
SIGN00331: D37.C IC4.5 R174.1 TP10.1 | length 8.9
  TOP w0.8: IC4.5@158.5,61.75 158.5,60.85 158.95,60.4 161.4,60.4 TP10.1@162,61 R174.1@162,63 162.15,62.85 D37.C@164,62.85
SIGN00332: D38.A R35.2 | length 1.9
  TOP w0.8: D38.A@189,65.15 R35.2@189,67
SIGN00334: R31.2 R174.2 | length 2
  TOP w0.8: R174.2@162,65 R31.2@162,67
SIGN00335: R34.2 R177.2 | length 2
  TOP w0.8: R177.2@187,65 R34.2@187,67
SIGN00336: D38.C IC5.5 R177.1 TP13.1 | length 8.9
  TOP w0.8: IC5.5@183.5,61.75 183.5,60.85 183.95,60.4 186.4,60.4 TP13.1@187,61 R177.1@187,63 187.15,62.85 D38.C@189,62.85
SIGN00418: IC9.7 Q11.G R180.1 | length 101.9
  TOP w0.3: IC9.7@135.2,42.175 135.875,42.175 136.1,42.4 136.1,45.25 136.6,45.75 140.25,45.75 140.55,45.45 R180.1@140.55,44.8 140.55,44.05 141.425,43.175 157.875,43.175 159.8,45.1 186.8,45.1 187.8,46.1 191.5,46.1 194.8,49.4 204.98,49.4 208.1,46.28 208.1,45.356 208.906,44.55 209.83,44.55 211.43,42.95 219,42.95 222.75,46.7 223.5,46.7 223.75,46.95 Q11.G@223.75,47.85
SIGN00430: D40.A R43.2 | length 1.9
  TOP w0.8: D40.A@251,65.15 R43.2@251,67
SIGN00431: D40.C IC8.5 R185.1 TP19.1 | length 8.9
  TOP w0.8: IC8.5@245.5,61.75 245.5,60.85 245.95,60.4 248.4,60.4 TP19.1@249,61 R185.1@249,63 249.15,62.85 D40.C@251,62.85
SIGN00432: D39.C IC7.5 R182.1 TP16.1 | length 8.7
  TOP w0.8: IC7.5@220.5,61.75 220.5,60.85 220.95,60.4 223.4,60.4 TP16.1@224,61 224,62.85 D39.C@226,62.85
SIGN00433: D39.A R40.2 | length 1.9
  TOP w0.8: D39.A@226,65.15 R40.2@226,67
SIGN00434: R39.2 R182.2 | length 1.9
  TOP w0.8: R182.2@224,65.15 R39.2@224,67
SIGN00435: R42.2 R185.2 | length 2
  TOP w0.8: R185.2@249,65 R42.2@249,67
SIGN00510: C42.2 IC11.3 | length 2.1
  TOP w0.3: C42.2@30,115.25 30,117.206 IC11.3@30.095,117.301
SIGN00512: IC11.14 IC11.15 R48.1 TP74.1 | length 9.1
  TOP w0.3: TP74.1@25.5,129 R48.1@28.5,129 29.725,129 30.095,128.63 IC11.14@30.095,126.699
  TOP w0.75: R48.1@28.5,129 28.5,128 28.825,127.675 IC11.15@28.825,126.699
SIGN00514: Q13.3 R48.2
SIGN00515: Q14.3 R49.2
SIGN00516: IC11.8 IC11.9 R49.1 TP24.1 | length 15.4
  TOP w0.3: R49.1@36,129 TP24.1@39.5,129 ; IC11.8@36.445,117.301 IC11.9@36.445,126.699
  TOP w0.75: R49.1@36,129 36.445,128.555 IC11.9@36.445,126.699
SIGN00523: C45.1 C46.2 L1.2 TP26.1 | length 8.3
  TOP w1: C45.1@30.5,137 C46.2@30.5,139 TP26.1@33,139 32.73,140.015 L1.2@32.73,142.75
SIGN00525: L1.4 T1.1 | length 16.3
  TOP w1: L1.4@35.27,150.25 35.27,152.67 36.3,153.7 40.9,153.7 42.61,151.99 T1.1@42.61,146.555
SIGN00526: L1.3 T1.10 | length 13.5
  TOP w1: L1.3@32.73,150.25 32.73,152.73 35.445,155.445 T1.10@42.61,155.445
SIGN00535: C40.1 D13.C IC11.16 TP22.1 | length 10.8
  TOP w0.3: D13.C@25.5,122.15 23.55,122.15 23,122.7 TP22.1@23,125 24.02,125.25 C40.1@25.5,125.25 25.5,126.318 25.881,126.699 IC11.16@27.555,126.699
SIGN00537: IC11.11 L1.1 Q14.1 Q14.2 Q14.5 Q14.6 R50.1 | length 24.7
  TOP w0.6: R50.1@33.75,134 Q14.2@35.25,134 Q14.5@37.75,134 ; R50.1@33.775,134.95 Q14.1@35.25,134.95 Q14.6@37.75,134.95
  TOP w0.75: R50.1@33.75,134 33.75,131.7 33.905,131.545 IC11.11@33.905,126.699
  TOP w0.8: R50.1@33.75,134 33.75,136.484
  TOP w1: 33.75,136.484 33.75,137.55 35.27,139.07 L1.1@35.27,142.75
SIGN00538: IC11.6 J13.2 J14.2 TP23.1 | length 11
  TOP w0.6: J14.2@30.55,109.4 J13.2@32.55,109.4 32.55,110.55 34.5,112.5 TP23.1@34.5,114
  TOP w0.75: IC11.6@33.905,117.301 33.905,114.595 TP23.1@34.5,114
SIGN00539: IC30.5 J14.1 R161.2 | length 5
  TOP w0.6: R161.2@27,106.25 28.75,106.25 29.05,106.55 IC30.5@29.05,107.315 J14.1@29.05,109.4
SIGN00540: C135.2 IC30.1 R161.1 | length 4.7
  TOP w0.6: R161.1@27,104.75 C135.2@27,103.25 28.55,103.25 29.05,103.75 IC30.1@29.05,104.685
SIGN00541: C40.2 IC11.12 IC11.13 Q13.4 R50.2 TP25.1 | length 17.5
  TOP w0.5: C40.2@25.5,123.75 30.075,123.75 31.365,125.04 IC11.13@31.365,126.699
  TOP w0.6: 30.75,132.2 Q13.4@30.75,133.05 R50.2@32.25,133.05
  TOP w0.75: IC11.13@31.365,126.699 31.365,127.85 ; 32.25,131.85 32.635,131.465 IC11.12@32.635,126.699
  TOP w0.8: R50.2@32.25,133.35 R50.2@32.25,134
SIGN00610: C55.2 D19.C R54.2 R55.1 | length 13.3
  TOP w1: D19.C@90.5,142.411 90.5,144.075 91.825,145.4 96,145.4 96.5,144.9 C55.2@96.5,144 R54.2@98.5,144 R55.1@100.5,144
SIGN00611: DS2.A R54.1 | length 2
  TOP w1: DS2.A@96.55,142 R54.1@98.5,142
SIGN00612: C54.2 D19.A D20.C | length 4.1
  TOP w0.8: D19.A@90.5,139.85 D20.C@92.5,139.85 94.15,139.85 C54.2@94.5,139.5
SIGN00616: C56.2 D21.C IC13.1 IC13.5 R56.2 | length 6
  TOP w0.35: IC13.1@102.35,140.05 IC13.5@102.35,141.95
  TOP w0.8: D21.C@96.5,139.65 96.85,140 R56.2@98.5,140
  TOP w1: R56.2@98.5,140 C56.2@100.5,140
SIGN00621: C50.2 IC12.3 | length 2
  TOP w0.3: C50.2@75,123.75 75.6,124.35 IC12.3@76.75,124.35
SIGN00622: C57.2 IC13.3 | length 2
  TOP w0.3: IC13.3@103.65,140.05 103.65,138.9 C57.2@104.25,138.3
SIGN00623: C47.2 D14.A D15.C | length 3.8
  TOP w0.8: C47.2@74.7,135.5 D15.C@76.55,135.5 D14.A@76.55,137.5
SIGN00711: DS4.A R60.1 | length 2
  TOP w1: R60.1@61.5,129.5 DS4.A@61.5,131.45
SIGN00715: C63.2 D25.C IC14.1 IC14.5 R59.2 | length 6
  TOP w0.35: IC14.1@102.35,157.25 IC14.5@102.35,159.15
  TOP w0.8: D25.C@96.5,156.85 96.85,157.2 R59.2@98.5,157.2
  TOP w1: R59.2@98.5,157.2 C63.2@100.5,157.2
SIGN00718: C69.2 D27.C R60.2 R61.1 | length 13.3
  TOP w1: D27.C@61.911,137.5 63.575,137.5 64.9,136.175 64.9,132 64.4,131.5 C69.2@63.5,131.5 R60.2@63.5,129.5 R61.1@63.5,127.5
SIGN00721: C64.2 IC14.3 | length 2
  TOP w0.3: IC14.3@103.65,157.25 103.65,156.1 C64.2@104.25,155.5
SIGN00722: C71.2 IC15.3 | length 2
  TOP w0.3: C71.2@57.8,123.75 58.4,124.35 IC15.3@59.55,124.35
SIGN00723: C68.2 D27.A D28.C | length 3.8
  TOP w0.8: C68.2@57.5,135.5 D28.C@59.35,135.5 D27.A@59.35,137.5
SIGN00885: C100.1 IC16.2 R104.1 | length 5.1
  TOP w0.8: R104.1@89.5,67 90.25,66.25 C100.1@90.25,64.5 90.25,63.215 90.135,63.1 IC16.2@90.135,62.3
SIGN00887: C105.1 IC17.2 R106.1 | length 5.1
  TOP w0.8: R106.1@151.5,67 152.25,66.25 C105.1@152.25,64.5 152.25,63.215 152.135,63.1 IC17.2@152.135,62.3
SIGN00979: R67.2 R68.1
SIGN00980: R68.2 R69.1
SIGN00981: R69.2 R70.1
SIGN00982: R63.2 R70.2 R71.1 | length 3.7
  TOP w0.5: R70.2@69.25,73.075 69,72.825 R63.2@69,71 R71.1@70.5,71
SIGN00983: R66.2 R67.1
SIGN00994: D31.C R78.2 | length 1.6
  TOP w0.3: R78.2@99,32.5 D31.C@100.65,32.5
SIGN00995: D32.A R79.2 | length 1.6
  TOP w0.3: R79.2@99,34.5 D32.A@100.65,34.5
SIGN00997: D33.C R80.2 | length 1.6
  TOP w0.3: R80.2@99,28.5 D33.C@100.65,28.5
SIGN00998: D34.A R81.2 | length 1.6
  TOP w0.3: R81.2@99,30.5 D34.A@100.65,30.5
SIGN00999: D35.C R82.2 | length 1.6
  TOP w0.3: R82.2@99,24.5 D35.C@100.65,24.5
SIGN01044: Q15.G R109.1 R110.1 | length 3.4
  TOP w0.3: Q15.G@116.95,36.85 117.25,36.85 117.85,36.25 R109.1@118.4,36.25 118.4,35.4 R110.1@119,34.8
SIGN008104: C110.1 IC18.2 R108.1 | length 5.1
  TOP w0.8: R108.1@213.5,67 214.25,66.25 C110.1@214.25,64.5 214.25,63.215 214.135,63.1 IC18.2@214.135,62.3
SIGN008118: IC16.6 R138.2 | length 2.6
  TOP w0.3: R138.2@88.5,49.25 88.865,49.615 IC16.6@88.865,51.7
SIGN008121: C155.1 IC22.2 R127.1 R128.2 | length 7.4
  TOP w0.3: IC22.2@203.2,36.675 204.025,36.675 204.45,37.1 204.45,39 204.7,39.25 R128.2@205.5,39.25 ; R127.1@205.5,40.75 R128.2@205.5,39.25 ; C155.1@206.9,39.25 R128.2@205.5,39.25
SIGN008122: R128.1 R129.2 | length 1.5
  TOP w0.3: R129.2@205.5,36.25 R128.1@205.5,37.75
SIGN008125: IC17.7 R130.2 | length 2.5
  TOP w0.3: R130.2@152,49.25 152.135,49.385 IC17.7@152.135,51.7
SIGN008126: IC17.6 R131.2 | length 2.6
  TOP w0.3: R131.2@150.5,49.25 150.865,49.615 IC17.6@150.865,51.7
SIGN008133: C151.2 IC20.1 R125.1 R127.2 | length 6
  TOP w0.3: IC20.1@203.2,44.525 205.225,44.525 R125.1@205.5,44.25 R127.2@205.5,42.25 206.4,42.25 C151.2@206.9,42.75
SIGN008134: R135.1 R136.2 | length 1.5
  TOP w0.3: R136.2@198,36.25 R135.1@198,37.75
SIGN008136: R142.1 R143.2 | length 2.3
  TOP w0.3: R142.1@64.1,47.05 65.05,47.05 65.45,46.65 R143.2@65.45,45.9
SIGN008137: IC18.7 R123.2 | length 2.5
  TOP w0.3: R123.2@214,49.25 214.135,49.385 IC18.7@214.135,51.7
SIGN008138: IC18.6 R124.2 | length 2.6
  TOP w0.3: R124.2@212.5,49.25 212.865,49.615 IC18.6@212.865,51.7
SIGN008139: IC19.7 R144.2 | length 2
  TOP w0.8: R144.2@41.25,106.5 41.385,106.365 IC19.7@43.2,106.365
SIGN008140: IC19.6 R145.2 | length 2.1
  TOP w0.8: R145.2@41.25,108 41.385,108 41.75,107.635 IC19.6@43.2,107.635
SIGN008145: C157.2 IC21.1 R139.1 R141.2 | length 5.8
  TOP w0.3: IC21.1@55.475,41.7 55.475,42.325 55.75,42.6 R139.1@55.75,44.5 ; C157.2@55.75,45.9 R139.1@55.75,44.5 ; R141.2@57.25,44.5 R139.1@55.75,44.5
SIGN008146: C161.1 IC23.2 R141.1 R142.2 | length 11.4
  TOP w0.3: v2(58.75,43) R141.1@58.75,44.5 ; IC23.2@63.325,41.7 63.325,42.626 v2(63.1,43.1) 62.7,43.5 62.7,43.95 C161.1@62.45,44.2 62.45,45.1 62.9,45.55 R142.2@64.1,45.55
  Mid-Layer 2 w0.3: v2(58.75,43) 62.508,43 v2(63.1,43.1)
SIGN008147: IC23.5 IC31.3 R121.2 R122.1 | length 16.4
  TOP w0.3: R122.1@60.6,36.25 60.65,36.3 R121.2@62.15,36.3 ; IC23.5@62.025,38.3 62.025,36.425 R121.2@62.15,36.3 ; IC31.3@71,38.95 70.2,38.95 69.85,38.6 69.85,36.05 69.05,35.25 62.35,35.25 62.15,35.45 R121.2@62.15,36.3
SIGN008148: C156.1 IC22.6 R134.1 R135.2 | length 6.3
  TOP w0.3: C156.1@196.6,39.25 R135.2@198,39.25 ; R134.1@198,40.75 R135.2@198,39.25 ; IC22.6@199.8,37.325 199.05,37.325 198.9,37.475 198.9,38.85 198.5,39.25 R135.2@198,39.25
SIGN008149: C100.2 IC16.3 R103.1 | length 5.3
  TOP w0.8: R103.1@87.5,67 87.5,65.75 C100.2@88.75,64.5 88.75,63.215 88.865,63.1 IC16.3@88.865,62.3
SIGN008150: C105.2 IC17.3 R105.1 | length 5.3
  TOP w0.8: R105.1@149.5,67 149.5,65.75 C105.2@150.75,64.5 150.75,63.215 150.865,63.1 IC17.3@150.865,62.3
SIGN008151: C110.2 IC18.3 R107.1 | length 5.3
  TOP w0.8: R107.1@211.5,67 211.5,65.75 C110.2@212.75,64.5 212.75,63.215 212.865,63.1 IC18.3@212.865,62.3
SIGN008153: C151.1 IC20.2 R123.1 R125.2 | length 16.5
  TOP w0.3: IC20.2@203.2,45.175 204.175,45.175 204.75,45.75 R125.2@205.5,45.75 ; v2(205.5,46.9) R125.2@205.5,45.75 ; C151.1@206.9,44.25 206.9,45.45 206.6,45.75 R125.2@205.5,45.75 ; v2(213.5,46.7) 214,47.2 R123.1@214,47.75
  Mid-Layer 2 w0.3: v2(205.5,46.9) 206.55,45.85 212.65,45.85 v2(213.5,46.7)
SIGN008154: C152.1 IC20.6 R130.1 R133.2 | length 58.1
  TOP w0.3: v2(150.5,46.4) 151.754,46.4 152,46.646 R130.1@152,47.75 ; R133.2@196.6,44.25 196.75,44.4 v2(196.75,45.75) C152.1@198,45.75 198.075,45.825 IC20.6@199.8,45.825
  BOTTOM w0.3: v2(150.5,46.4) 150.5,45.4 152,43.9 157.5,43.9 158.55,44.95 185.85,44.95 188.35,42.45 193.45,42.45 v2(196.75,45.75)
SIGN008155: C153.2 IC20.3 R124.1 R126.1 | length 17.5
  TOP w0.3: v2(202,45.2) 202.273,45.648 202.45,45.825 IC20.3@203.2,45.825 ; v2(212.2,46.7) 211.9,46.4 C153.2@211.15,46.4 211.15,47.6 R126.1@211,47.75 R124.1@212.5,47.75
  Mid-Layer 2 w0.3: v2(202,45.2) 204.55,47.75 205.9,47.75 207.2,46.45 211.655,46.45 v2(212.2,46.7)
SIGN008156: C154.2 IC20.5 R131.1 R132.1 | length 63.4
  TOP w0.3: v2(149,46.4) 148.5,46.4 147.7,47.2 C154.2@147.7,47.75 R132.1@149.1,47.75 R131.1@150.5,47.75 ; v2(196.75,47) 198.35,47 198.875,46.475 IC20.5@199.8,46.475
  BOTTOM w0.3: v2(149,46.4) 149,46 151.7,43.3 157.8,43.3 158.85,44.35 185.55,44.35 188.125,41.775 194.05,41.775 197.6,45.325 197.6,46.15 v2(196.75,47)
SIGN008160: C160.2 IC21.5 R145.1 R146.1 | length 86.2
  TOP w0.3: v2(38.5,107.75) 39.5,107.75 R145.1@39.75,108 ; v2(53.3,37) 53.525,37.474 IC21.5@53.525,38.3
  TOP w0.8: C160.2@38.1,109.75 R146.1@39.5,109.75 39.75,109.5 R145.1@39.75,108
  Mid-Layer 2 w0.3: v2(38.5,107.75) 39.35,106.9 39.35,105.95 39.1,105.7 39.1,50.75 40.15,49.7 40.15,46.45 45.35,41.25 50.7,41.25 53.3,38.65 v2(53.3,37)
SIGN008161: IC23.6 IC23.7 R189.1 | length 2.3
  TOP w0.3: IC23.6@62.675,38.3 62.675,39.45 ; IC23.7@63.325,38.3 63.325,39.4
SIGN008162: IC31.1 IC31.4 R190.1 | length 11.6
  TOP w0.3: IC31.4@68.6,38.95 69.35,38.95 70.3,39.9 R190.1@70.3,40.8 72.65,40.8 73.85,39.6 73.85,38.4 72.5,37.05 IC31.1@71,37.05
SIGN008163: C157.1 IC21.2 R137.1 R139.2 | length 48.2
  TOP w0.3: v2(53.2,44.5) R139.2@54.25,44.5 ; R139.2@54,44.25 R139.2@54.25,44.5 ; C157.1@54.25,45.9 R139.2@54.25,44.5 ; IC21.2@54.825,41.7 54.825,43.225 54.25,43.8 R139.2@54.25,44.5 ; v2(90,46.7) R137.1@90,47.75
  BOTTOM w0.3: v2(53.2,44.5) 56.1,44.5 62.35,50.75 86.4,50.75 90,47.15 v2(90,46.7)
SIGN008164: C159.2 IC21.3 R138.1 R140.1 | length 45.3
  TOP w0.3: v2(53.7,43.1) 54.175,42.625 IC21.3@54.175,41.7 ; C159.2@86.95,46.4 86.95,47.7 R140.1@87,47.75 R138.1@88.5,47.75 v2(88.5,46.7)
  BOTTOM w0.3: v2(53.7,43.1) 54.5,43.9 56.35,43.9 62.6,50.15 86.15,50.15 88.5,47.8 v2(88.5,46.7)
SIGN008165: C158.1 IC21.6 R144.1 R147.2 | length 86.7
  TOP w0.3: v2(38.5,106.5) R144.1@39.75,106.5 ; v2(52.6,35.5) R147.2@53.75,35.5 ; C158.1@53.75,34.1 R147.2@53.75,35.5 ; IC21.6@54.175,38.3 54.175,36.744 53.75,36.319 R147.2@53.75,35.5
  Mid-Layer 2 w0.3: v2(38.5,106.5) 38.5,50.5 39.45,49.55 39.45,46.3 45.1,40.65 50.45,40.65 52.45,38.65 52.45,36.081 v2(52.6,35.5)
SIGN008167: C95.1 IC19.2 R102.1 | length 4.4
  TOP w0.8: IC19.2@53.8,106.365 55.435,106.365 55.55,106.25 C95.1@56.5,106.25 57.75,106.25 R102.1@58,106.5
SIGN008168: C95.2 IC19.3 R101.1 | length 4.6
  TOP w0.8: IC19.3@53.8,107.635 55.4,107.635 55.515,107.75 C95.2@56.5,107.75 57.25,108.5 R101.1@58,108.5
SIGN008169: IC16.7 R137.2 | length 2.5
  TOP w0.3: R137.2@90,49.25 90.135,49.385 IC16.7@90.135,51.7
SIGN009100: D36.A R83.2 | length 1.6
  TOP w0.3: R83.2@99,26.5 D36.A@100.65,26.5
SIGN009104: IC27.2 R84.1 R85.1 | length 7.9
  TOP w0.3: R85.1@83.5,28 84.6,26.9 85.45,26.9 85.675,27.125 IC27.2@85.675,27.8 85.675,28.675 85.9,28.9 88.6,28.9 R84.1@89,28.5
SIGN009110: IC28.2 R92.1 | length 3.1
  TOP w0.3: R92.1@107.5,35.5 108.175,34.825 IC28.2@110.3,34.825
SIGN009111: IC27.5 R93.1 R94.2 | length 6.7
  TOP w0.3: IC27.5@86.975,31.2 86.975,30.375 87.3,30.05 88.75,30.05 89,30.3 R93.1@89,30.5 89,31.65 88,32.65 R94.2@88,33.5
SIGN009116: C91.2 IC27.3 R86.2 R87.1 TP54.1 | length 8.8
  TOP w0.3: IC27.3@86.325,27.8 86.325,25.575 C91.2@86.25,25.5 85.75,26 R87.1@84.75,26 84.75,24.52 TP54.1@84.5,23.5 R86.2@86.75,23.5
SIGN009117: C92.2 IC27.6 R88.2 R89.1 TP55.1 | length 8.3
  TOP w0.3: IC27.6@86.325,31.2 86.325,31.975 86.5,32.15 86.5,33.75 C92.2@86.25,34 R89.1@86.25,35.5 ; TP55.1@86.5,37.8 86.25,36.78 R89.1@86.25,35.5 ; R88.2@87.75,35.5 R89.1@86.25,35.5
SIGN009124: R78.1 R80.1 R82.1 R84.2 TP51.1 | length 19.2
  TOP w0.3: R84.2@91,28.5 91.9,28.5 92.9,27.5 TP51.1@94,27.5 ; R82.1@97,24.5 95.225,24.5 94,25.725 TP51.1@94,27.5 ; R80.1@97,28.5 95,28.5 TP51.1@94,27.5 ; R78.1@97,32.5 95.575,32.5 95.15,32.075 95.15,30.975 94,29.825 TP51.1@94,27.5
SIGN009125: R79.1 R81.1 R83.1 R93.2 TP52.1 | length 17.3
  TOP w0.3: R93.2@91,30.5 93,30.5 TP52.1@94,31.5 94,33.2 95.3,34.5 R79.1@97,34.5 ; v2(95.75,27) 96.5,27 R83.1@97,26.5 ; v2(95.75,29.75) 95.75,30.417 95.833,30.5 R81.1@97,30.5
  Mid-Layer 2 w0.3: TP52.1@94,31.5 v2(95.75,29.75) v2(95.75,27)
SIGN009127: C93.2 IC28.3 R90.2 R91.1 TP57.1 | length 12.7
  TOP w0.3: R90.2@105.75,39 104.65,37.9 104.65,34.039 TP57.1@104.5,33 105.52,33.25 R91.1@107,33.25 C93.2@108.5,33.25 109.425,34.175 IC28.3@110.3,34.175
SIGN009128: C94.2 IC28.5 R95.2 R96.1 TP58.1 | length 9.4
  TOP w0.3: IC28.5@113.7,33.525 112.975,33.525 112.85,33.4 112.85,32.4 C94.2@113.25,32 R96.1@113.25,30.5 TP58.1@115.5,30.5 116.5,31.5 R95.2@116.5,33.25
SIGN009129: IC26.4 R114.2 R115.2 | length 7.2
  TOP w0.3: R114.2@179.5,38.5 179.5,38.3 178.9,37.7 178.9,35.5 179.2,35.2 179.8,35.2 IC26.4@179.95,35.05 179.95,33.75 180.25,33.45 R115.2@180.25,32.5
SIGN009130: IC26.1 R114.1 R116.1 | length 3.9
  TOP w0.3: IC26.1@177.55,36.95 176.85,36.95 176.5,37.3 R116.1@176.5,38.5 R114.1@178,38.5
SIGN009131: IC26.3 R112.2 R113.1 | length 5.6
  TOP w0.3: R112.2@177.5,31.5 R113.1@177.5,33.5 178.45,33.5 178.7,33.75 178.7,34.8 178.45,35.05 IC26.3@177.55,35.05
SIGN009132: C75.2 IC24.3 R63.1 TP50.1 | length 16.6
  TOP w0.5: TP50.1@64.5,71 R63.1@67,71 ; v2(70,64.75) 71,64.75 C75.2@71.25,64.5 71.365,64.385 IC24.3@71.365,62.3
  Mid-Layer 2 w0.5: TP50.1@64.5,71 64.5,66.9 66.65,64.75 v2(70,64.75)
SIGN009135: IC24.6 R149.2 | length 2.1
  TOP w0.3: R149.2@71,49.75 71.365,50.115 IC24.6@71.365,51.7
SIGN009139: C165.1 IC25.5 R152.1 R153.1 | length 7.5
  TOP w0.3: R152.1@44,39.25 44.05,39.2 C165.1@44.05,37.8 45.125,36.725 47.025,36.725 ; IC25.5@47.025,38.3 47.025,36.725 ; R153.1@47.75,36 47.025,36.725
SIGN009140: C162.2 IC25.1 R150.1 R156.2 | length 8.6
  TOP w0.3: R156.2@45.5,41.25 45.7,41.25 46.25,40.7 48.75,40.7 48.975,40.925 IC25.1@48.975,41.7 48.975,42.075 49.75,42.85 R150.1@49.75,44 49.7,44.05 C162.2@49.7,45.35
SIGN009143: C164.1 IC25.6 R155.2 R156.1 | length 12.5
  TOP w0.3: v2(45.5,38.6) R156.1@45.5,39.75 47.4,39.75 47.675,39.475 IC25.6@47.675,38.3 ; C164.1@46.35,35.7 46.35,35.65 v2(47.5,34.5) R155.2@48.75,34.5
  Mid-Layer 2 w0.3: v2(45.5,38.6) 47.5,36.6 v2(47.5,34.5)
SIGN009144: IC24.7 R148.2 | length 2
  TOP w0.3: R148.2@72.5,49.75 72.635,49.885 IC24.7@72.635,51.7
SIGN009145: C118.2 IC29.2 IC29.6 R97.2 R98.1 TP61.1 | length 12.4
  TOP w0.3: IC29.2@170.675,34.3 170.675,35.275 171.325,35.925 IC29.6@171.325,37.7 171.325,39.925 R97.2@171.25,40 C118.2@171.25,41.5 172.6,41.5 TP61.1@173.5,41 R98.1@176,41
SIGN009146: C115.2 IC29.3 J1.1 R111.2 R112.1 TP59.1 | length 23.2
  TOP w0.3: IC29.3@171.325,34.3 171.325,32.535 TP59.1@171.5,31.5 R112.1@175.5,31.5 175.5,30.6 175.7,30.4 182.65,30.4 R111.2@185.5,33.25 C115.2@187,33.25 188,33.25 J1.1@189.25,32
SIGN009147: C163.2 IC25.3 R148.1 R151.1 | length 36.1
  TOP w0.3: IC25.3@47.675,41.7 47.675,42.924 47,43.599 47,45.05 C163.2@47.3,45.35 47.95,45.35 48.2,45.6 48.2,48.15 48.05,48.3 R151.1@47.25,48.3 47.25,49.2 47.55,49.5 v2(48.1,49.5) ; v2(49.75,49.5) 67.625,49.5 69.725,47.4 71.65,47.4 R148.1@72.5,48.25
  BOTTOM w0.3: v2(48.1,49.5) v2(49.75,49.5)
SIGN009148: C162.1 IC25.2 R149.1 R150.2 | length 32.5
  TOP w0.3: IC25.2@48.325,41.7 48.325,43.925 R150.2@48.25,44 48.25,44.7 48.8,45.25 48.8,46.4 49.25,46.85 C162.1@49.7,46.85 49.7,48.05 48.9,48.85 48.9,49.825 49.375,50.3 67.675,50.3 69.725,48.25 R149.1@71,48.25
SIGN009149: R155.1 R157.2 | length 1.5
  TOP w0.3: R157.2@50.25,33 R155.1@50.25,34.5
SIGN009150: R153.2 R154.2 | length 5.2
  TOP w0.3: R153.2@49.25,36 50.625,36 52,37.375 R154.2@52,39.25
